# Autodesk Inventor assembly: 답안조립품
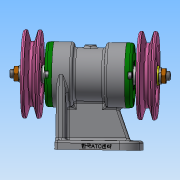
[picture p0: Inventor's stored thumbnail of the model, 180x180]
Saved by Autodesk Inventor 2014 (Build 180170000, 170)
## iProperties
Created: 2020-06
Part Number: 답안조립품
Document SubType Name: Assembly
Designer: NET
Author: NET
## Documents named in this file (12)
- C:\Users\NET\Desktop\700606V1055\답안조립품.iam
- C:\Users\NET\Desktop\700606V1055\본체.ipt
- C:\Users\NET\Desktop\700606V1055\V-벨트풀리.ipt
- C:\Users\NET\Desktop\700606V1055\너트 M10.ipt
- C:\Users\NET\Desktop\700606V1055\베어링 6204.ipt
- C:\Users\NET\Desktop\700606V1055\볼트 M4.ipt
- C:\Users\NET\Desktop\700606V1055\스프링 와셔 10.ipt
- C:\Users\NET\Desktop\700606V1055\오일 실 20 32 5.ipt
- C:\Users\NET\Desktop\700606V1055\축.ipt
- C:\Users\NET\Desktop\700606V1055\커버.ipt
- C:\Users\NET\Desktop\700606V1055\키 5x5x12.ipt
- C:\Users\NET\Desktop\700606V1055\평면 와셔 10x21.ipt
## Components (2 placed, 1 different names)
1. V-벨트풀리:1
2. V-벨트풀리:2
